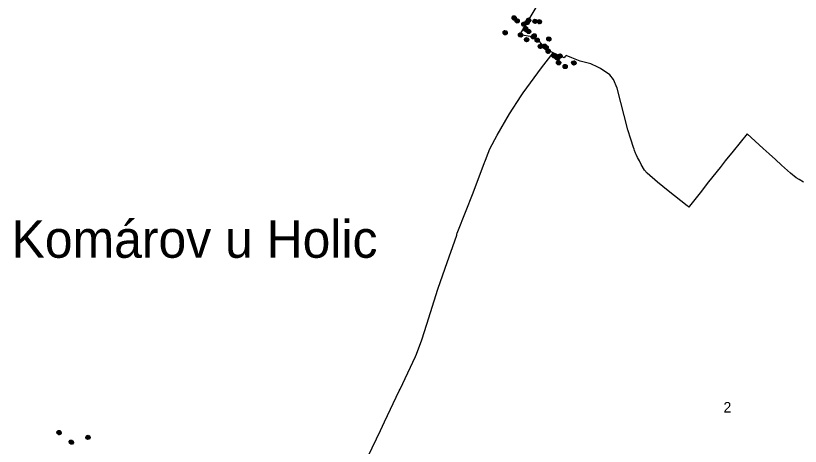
# Model space of a CAD drawing. Extents: x -636174 to -630484, y -1066390 to -1059369.
# Drawn here: x -635533 to -633008, y -1062153 to -1060768 of the extents above; entities that cross this region are included whole.
import ezdxf

# ---------------------------------------------------------------- set-up
doc = ezdxf.new("R2010")
doc.units = 0
for name, color, linetype in [('HRA_KU', 7, 'Continuous'), ('KU_OST', 7, 'Continuous'), ('Level 255', 7, 'Continuous'), ('OVNE_PRE', 7, 'Continuous'), ('OVNE_SET', 7, 'Continuous')]:
    doc.layers.add(name, color=color, linetype=linetype)

msp = doc.modelspace()

# ---------------------------------------------------------------- linework, layer by layer
at = {"layer": 'HRA_KU'}
for points in [[(-633803.1, -1060886.9), (-633821.3, -1060878), (-633833.6, -1060866.4), (-633848.8, -1060849.5), (-633858.7, -1060840.4), (-633863.1, -1060836.3), (-633910.6, -1060829.4), (-633834.8, -1060701.1)], [(-633935.3, -1060777.9), (-633935.4, -1060772.5), (-633931.8, -1060768.6), (-633926.4, -1060768.4), (-633922.4, -1060772.1), (-633922.2, -1060777.4), (-633925.9, -1060781.4), (-633931.3, -1060781.6), (-633935.3, -1060777.9), (-633934.3, -1060777.7), (-633930.7, -1060781), (-633928.5, -1060780.9), (-633934.3, -1060775.5), (-633934.4, -1060773.2), (-633926.2, -1060780.8), (-633925.1, -1060779.7), (-633933.3, -1060772), (-633932.3, -1060770.9), (-633924, -1060778.5), (-633923, -1060777.3), (-633931.2, -1060769.7), (-633928.9, -1060769.6), (-633923, -1060775.1), (-633923.1, -1060772.8), (-633926.6, -1060769.5)], [(-633925.4, -1060787.1), (-633925.6, -1060781.7), (-633921.9, -1060777.8), (-633916.6, -1060777.6), (-633912.6, -1060781.3), (-633912.4, -1060786.6), (-633916.1, -1060790.6), (-633921.5, -1060790.8), (-633925.4, -1060787.1), (-633924.4, -1060786.9), (-633920.9, -1060790.2), (-633918.7, -1060790.1), (-633924.5, -1060784.7), (-633924.6, -1060782.4), (-633916.4, -1060790), (-633915.3, -1060788.9), (-633923.5, -1060781.2), (-633922.4, -1060780.1), (-633914.2, -1060787.7), (-633913.1, -1060786.5), (-633921.3, -1060778.9), (-633919.1, -1060778.8), (-633913.2, -1060784.3), (-633913.3, -1060782), (-633916.8, -1060778.7)], [(-633904.2, -1060797.3), (-633903.9, -1060792), (-633899.9, -1060788.4), (-633894.6, -1060788.6), (-633891, -1060792.7), (-633891.2, -1060798), (-633895.3, -1060801.6), (-633900.6, -1060801.3), (-633904.2, -1060797.3), (-633903.2, -1060797.2), (-633900, -1060800.8), (-633897.8, -1060800.9), (-633903.1, -1060795), (-633903, -1060792.7), (-633895.5, -1060801.1), (-633894.3, -1060800), (-633901.8, -1060791.7), (-633900.6, -1060790.6), (-633893.1, -1060798.9), (-633891.9, -1060797.9), (-633899.4, -1060789.5), (-633897.2, -1060789.6), (-633891.8, -1060795.6), (-633891.7, -1060793.3), (-633894.9, -1060789.8)], [(-633891.4, -1060784.3), (-633886.2, -1060783), (-633881.6, -1060785.8), (-633880.2, -1060791), (-633883, -1060795.6), (-633888.2, -1060796.9), (-633892.8, -1060794.2), (-633894.2, -1060789), (-633891.4, -1060784.3), (-633890.8, -1060784.9), (-633893.3, -1060789.1), (-633892.7, -1060791.2), (-633888.6, -1060784.4), (-633886.4, -1060783.8), (-633892.1, -1060793.4), (-633890.8, -1060794.3), (-633885.1, -1060784.6), (-633883.7, -1060785.4), (-633889.4, -1060795.1), (-633888, -1060795.9), (-633882.3, -1060786.2), (-633881.8, -1060788.4), (-633885.8, -1060795.3), (-633883.6, -1060794.8), (-633881.2, -1060790.6)], [(-633886.8, -1060776.5), (-633881.6, -1060775.1), (-633876.9, -1060777.9), (-633875.6, -1060783.1), (-633878.3, -1060787.7), (-633883.5, -1060789.1), (-633888.2, -1060786.3), (-633889.5, -1060781.1), (-633886.8, -1060776.5), (-633886.2, -1060777.1), (-633888.6, -1060781.2), (-633888.1, -1060783.4), (-633884, -1060776.5), (-633881.8, -1060775.9), (-633887.5, -1060785.6), (-633886.1, -1060786.4), (-633880.4, -1060776.7), (-633879, -1060777.6), (-633884.7, -1060787.2), (-633883.4, -1060788), (-633877.7, -1060778.4), (-633877.1, -1060780.6), (-633881.2, -1060787.4), (-633879, -1060786.9), (-633876.5, -1060782.8)], [(-633867.1, -1060780.9), (-633862.2, -1060778.6), (-633857.1, -1060780.5), (-633854.9, -1060785.4), (-633856.8, -1060790.4), (-633861.6, -1060792.7), (-633866.7, -1060790.8), (-633869, -1060785.9), (-633867.1, -1060780.9), (-633866.4, -1060781.3), (-633868.1, -1060785.8), (-633867.1, -1060787.9), (-633864.4, -1060780.4), (-633862.3, -1060779.4), (-633866.2, -1060789.9), (-633864.7, -1060790.5), (-633860.8, -1060780), (-633859.3, -1060780.5), (-633863.2, -1060791), (-633861.7, -1060791.6), (-633857.8, -1060781.1), (-633856.9, -1060783.1), (-633859.6, -1060790.7), (-633857.6, -1060789.7), (-633855.9, -1060785.2)], [(-633853.2, -1060783.5), (-633848.7, -1060780.5), (-633843.4, -1060781.6), (-633840.5, -1060786), (-633841.5, -1060791.3), (-633846, -1060794.3), (-633851.3, -1060793.2), (-633854.3, -1060788.8), (-633853.2, -1060783.5), (-633852.5, -1060783.8), (-633853.4, -1060788.5), (-633852.1, -1060790.4), (-633850.6, -1060782.6), (-633848.7, -1060781.3), (-633850.9, -1060792.3), (-633849.3, -1060792.6), (-633847.1, -1060781.6), (-633845.6, -1060781.9), (-633847.8, -1060792.9), (-633846.2, -1060793.2), (-633844, -1060782.3), (-633842.7, -1060784.1), (-633844.3, -1060792), (-633842.4, -1060790.7), (-633841.5, -1060786)], [(-633898.6, -1060811.9), (-633898.8, -1060806.6), (-633895.1, -1060802.6), (-633889.8, -1060802.4), (-633885.8, -1060806.1), (-633885.6, -1060811.5), (-633889.3, -1060815.4), (-633894.7, -1060815.6), (-633898.6, -1060811.9), (-633897.9, -1060811.5), (-633894.4, -1060814.8), (-633892.1, -1060814.7), (-633898, -1060809.2), (-633898.1, -1060807), (-633889.9, -1060814.6), (-633888.8, -1060813.4), (-633897, -1060805.8), (-633895.9, -1060804.6), (-633887.7, -1060812.3), (-633886.6, -1060811.1), (-633894.8, -1060803.5), (-633892.6, -1060803.4), (-633886.7, -1060808.8), (-633886.8, -1060806.6), (-633890.3, -1060803.3)], [(-633897.5, -1060815.1), (-633897.7, -1060809.8), (-633894, -1060805.8), (-633888.6, -1060805.7), (-633884.7, -1060809.4), (-633884.5, -1060814.7), (-633888.2, -1060818.7), (-633893.6, -1060818.8), (-633897.5, -1060815.1), (-633896.5, -1060815), (-633893, -1060818.2), (-633890.8, -1060818.2), (-633896.6, -1060812.7), (-633896.7, -1060810.4), (-633888.5, -1060818.1), (-633887.4, -1060816.9), (-633895.6, -1060809.3), (-633894.5, -1060808.1), (-633886.3, -1060815.8), (-633885.2, -1060814.6), (-633893.4, -1060806.9), (-633891.1, -1060806.9), (-633885.3, -1060812.3), (-633885.4, -1060810.1), (-633888.9, -1060806.8)], [(-633888.8, -1060821.1), (-633889, -1060815.8), (-633885.3, -1060811.8), (-633879.9, -1060811.6), (-633876, -1060815.3), (-633875.8, -1060820.7), (-633879.5, -1060824.6), (-633884.8, -1060824.8), (-633888.8, -1060821.1), (-633888.1, -1060820.7), (-633884.6, -1060824), (-633882.3, -1060823.9), (-633888.2, -1060818.4), (-633888.3, -1060816.2), (-633880.1, -1060823.8), (-633879, -1060822.6), (-633887.2, -1060815), (-633886.1, -1060813.8), (-633877.9, -1060821.5), (-633876.8, -1060820.3), (-633885, -1060812.7), (-633882.7, -1060812.6), (-633876.9, -1060818), (-633877, -1060815.8), (-633880.5, -1060812.5)], [(-633961.6, -1060828.6), (-633964.8, -1060824.3), (-633964, -1060818.9), (-633959.7, -1060815.7), (-633954.4, -1060816.5), (-633951.2, -1060820.8), (-633951.9, -1060826.1), (-633956.2, -1060829.4), (-633961.6, -1060828.6), (-633960.9, -1060827.9), (-633956.1, -1060828.6), (-633954.3, -1060827.2), (-633962.2, -1060826.1), (-633963.6, -1060824.3), (-633952.5, -1060825.9), (-633952.3, -1060824.3), (-633963.4, -1060822.7), (-633963.1, -1060821.1), (-633952, -1060822.7), (-633951.8, -1060821.1), (-633962.9, -1060819.5), (-633961.1, -1060818.2), (-633953.2, -1060819.3), (-633954.5, -1060817.5), (-633959.3, -1060816.8)], [(-633912.1, -1060835.7), (-633915.3, -1060831.4), (-633914.5, -1060826.1), (-633910.2, -1060822.8), (-633904.9, -1060823.6), (-633901.7, -1060827.9), (-633902.4, -1060833.2), (-633906.7, -1060836.5), (-633912.1, -1060835.7), (-633911.8, -1060834.9), (-633907, -1060835.6), (-633905.2, -1060834.3), (-633913.1, -1060833.1), (-633914.5, -1060831.3), (-633903.4, -1060832.9), (-633903.2, -1060831.3), (-633914.3, -1060829.7), (-633914, -1060828.1), (-633902.9, -1060829.7), (-633902.7, -1060828.2), (-633913.8, -1060826.6), (-633912, -1060825.2), (-633904.1, -1060826.3), (-633905.4, -1060824.5), (-633910.2, -1060823.9)], [(-633894.4, -1060849.1), (-633896.1, -1060844.1), (-633893.8, -1060839.2), (-633888.7, -1060837.5), (-633883.8, -1060839.9), (-633882.1, -1060844.9), (-633884.5, -1060849.8), (-633889.6, -1060851.5), (-633894.4, -1060849.1), (-633893.5, -1060848.7), (-633889.2, -1060850.8), (-633887.1, -1060850.1), (-633894.2, -1060846.5), (-633895, -1060844.4), (-633884.9, -1060849.3), (-633884.2, -1060847.9), (-633894.3, -1060843), (-633893.6, -1060841.5), (-633883.5, -1060846.5), (-633882.8, -1060845), (-633892.9, -1060840.1), (-633890.7, -1060839.4), (-633883.5, -1060842.9), (-633884.3, -1060840.8), (-633888.6, -1060838.6)], [(-633870.6, -1060841.6), (-633873.8, -1060837.3), (-633873, -1060832), (-633868.7, -1060828.8), (-633863.4, -1060829.5), (-633860.2, -1060833.8), (-633860.9, -1060839.2), (-633865.2, -1060842.4), (-633870.6, -1060841.6), (-633869.9, -1060840.9), (-633865.1, -1060841.6), (-633863.3, -1060840.3), (-633871.2, -1060839.1), (-633872.6, -1060837.3), (-633861.5, -1060838.9), (-633861.3, -1060837.3), (-633872.3, -1060835.7), (-633872.1, -1060834.1), (-633861, -1060835.7), (-633860.8, -1060834.2), (-633871.9, -1060832.6), (-633870.1, -1060831.2), (-633862.2, -1060832.3), (-633863.5, -1060830.5), (-633868.3, -1060829.9)], [(-633870.8, -1060834.5), (-633870.6, -1060829.2), (-633866.5, -1060825.6), (-633861.2, -1060825.9), (-633857.6, -1060829.9), (-633857.9, -1060835.2), (-633861.9, -1060838.9), (-633867.2, -1060838.6), (-633870.8, -1060834.5), (-633870.1, -1060834.2), (-633866.9, -1060837.7), (-633864.7, -1060837.9), (-633870, -1060831.9), (-633869.9, -1060829.6), (-633862.4, -1060838), (-633861.2, -1060836.9), (-633868.7, -1060828.6), (-633867.5, -1060827.5), (-633860, -1060835.8), (-633858.8, -1060834.8), (-633866.3, -1060826.4), (-633864, -1060826.6), (-633858.7, -1060832.5), (-633858.6, -1060830.3), (-633861.8, -1060826.7)], [(-633861.1, -1060849.4), (-633861.3, -1060844), (-633857.6, -1060840.1), (-633852.2, -1060839.9), (-633848.3, -1060843.6), (-633848.1, -1060849), (-633851.8, -1060852.9), (-633857.2, -1060853.1), (-633861.1, -1060849.4), (-633860.4, -1060848.9), (-633856.9, -1060852.2), (-633854.6, -1060852.2), (-633860.5, -1060846.7), (-633860.5, -1060844.4), (-633852.4, -1060852.1), (-633851.3, -1060850.9), (-633859.4, -1060843.2), (-633858.4, -1060842.1), (-633850.2, -1060849.8), (-633849.1, -1060848.6), (-633857.3, -1060840.9), (-633855, -1060840.8), (-633849.2, -1060846.3), (-633849.2, -1060844.1), (-633852.7, -1060840.8)], [(-633821.1, -1060848.8), (-633824.3, -1060844.4), (-633823.5, -1060839.1), (-633819.2, -1060835.9), (-633813.9, -1060836.6), (-633810.7, -1060841), (-633811.4, -1060846.3), (-633815.7, -1060849.5), (-633821.1, -1060848.8), (-633820.8, -1060848), (-633816, -1060848.7), (-633814.2, -1060847.3), (-633822.1, -1060846.2), (-633823.5, -1060844.4), (-633812.4, -1060846), (-633812.2, -1060844.4), (-633823.2, -1060842.8), (-633823, -1060841.2), (-633811.9, -1060842.8), (-633811.7, -1060841.2), (-633822.8, -1060839.6), (-633821, -1060838.3), (-633813.1, -1060839.4), (-633814.4, -1060837.6), (-633819.2, -1060836.9)], [(-633849.6, -1060871.2), (-633851.3, -1060866.1), (-633848.9, -1060861.3), (-633843.8, -1060859.6), (-633839, -1060862), (-633837.2, -1060867), (-633839.6, -1060871.9), (-633844.7, -1060873.6), (-633849.6, -1060871.2), (-633849, -1060870.6), (-633844.7, -1060872.7), (-633842.6, -1060872), (-633849.7, -1060868.5), (-633850.5, -1060866.3), (-633840.4, -1060871.3), (-633839.7, -1060869.8), (-633849.8, -1060864.9), (-633849.1, -1060863.4), (-633839, -1060868.4), (-633838.3, -1060867), (-633848.4, -1060862), (-633846.2, -1060861.3), (-633839, -1060864.8), (-633839.8, -1060862.7), (-633844.1, -1060860.6)], [(-633837.1, -1060869.1), (-633837.3, -1060863.8), (-633833.6, -1060859.8), (-633828.3, -1060859.6), (-633824.3, -1060863.3), (-633824.1, -1060868.7), (-633827.8, -1060872.6), (-633833.2, -1060872.8), (-633837.1, -1060869.1), (-633836.1, -1060869), (-633832.6, -1060872.2), (-633830.3, -1060872.1), (-633836.2, -1060866.7), (-633836.3, -1060864.4), (-633828.1, -1060872.1), (-633827, -1060870.9), (-633835.2, -1060863.3), (-633834.1, -1060862.1), (-633825.9, -1060869.7), (-633824.8, -1060868.5), (-633833, -1060860.9), (-633830.8, -1060860.8), (-633824.9, -1060866.3), (-633825, -1060864), (-633828.5, -1060860.8)], [(-633832.7, -1060873.2), (-633832.9, -1060867.8), (-633829.2, -1060863.9), (-633823.8, -1060863.7), (-633819.9, -1060867.3), (-633819.7, -1060872.7), (-633823.3, -1060876.7), (-633828.7, -1060876.9), (-633832.7, -1060873.2), (-633831.7, -1060873), (-633828.2, -1060876.3), (-633825.9, -1060876.2), (-633831.8, -1060870.8), (-633831.9, -1060868.5), (-633823.6, -1060876.1), (-633822.6, -1060874.9), (-633830.8, -1060867.3), (-633829.7, -1060866.1), (-633821.5, -1060873.8), (-633820.4, -1060872.6), (-633828.6, -1060865), (-633826.3, -1060864.9), (-633820.5, -1060870.3), (-633820.5, -1060868.1), (-633824.1, -1060864.8)], [(-633825.9, -1060884.6), (-633825.6, -1060879.2), (-633821.6, -1060875.6), (-633816.2, -1060875.9), (-633812.6, -1060879.9), (-633812.9, -1060885.3), (-633816.9, -1060888.9), (-633822.3, -1060888.6), (-633825.9, -1060884.6), (-633824.9, -1060884.5), (-633821.7, -1060888.1), (-633819.4, -1060888.2), (-633824.8, -1060882.2), (-633824.7, -1060880), (-633817.2, -1060888.3), (-633816, -1060887.2), (-633823.5, -1060878.9), (-633822.3, -1060877.8), (-633814.8, -1060886.2), (-633813.6, -1060885.1), (-633821.1, -1060876.8), (-633818.8, -1060876.9), (-633813.5, -1060882.8), (-633813.4, -1060880.6), (-633816.6, -1060877)], [(-633807.8, -1060899.4), (-633808, -1060894.1), (-633804.3, -1060890.1), (-633798.9, -1060890), (-633795, -1060893.7), (-633794.8, -1060899), (-633798.5, -1060903), (-633803.9, -1060903.1), (-633807.8, -1060899.4), (-633806.8, -1060899.3), (-633803.3, -1060902.6), (-633801.1, -1060902.5), (-633806.9, -1060897), (-633807, -1060894.7), (-633798.8, -1060902.4), (-633797.7, -1060901.3), (-633805.9, -1060893.6), (-633804.8, -1060892.4), (-633796.6, -1060900.1), (-633795.5, -1060898.9), (-633803.7, -1060891.3), (-633801.4, -1060891.2), (-633795.6, -1060896.7), (-633795.7, -1060894.4), (-633799.2, -1060891.1)], [(-633787, -1060902), (-633788.7, -1060896.9), (-633786.3, -1060892.1), (-633781.2, -1060890.4), (-633776.4, -1060892.7), (-633774.7, -1060897.8), (-633777.1, -1060902.7), (-633782.1, -1060904.4), (-633787, -1060902), (-633786.1, -1060901.6), (-633781.8, -1060903.7), (-633779.6, -1060903), (-633786.8, -1060899.4), (-633787.5, -1060897.3), (-633777.5, -1060902.2), (-633776.8, -1060900.8), (-633786.8, -1060895.9), (-633786.1, -1060894.4), (-633776.1, -1060899.4), (-633775.4, -1060897.9), (-633785.4, -1060893), (-633783.3, -1060892.3), (-633776.1, -1060895.8), (-633776.8, -1060893.6), (-633781.1, -1060891.5)], [(-633800.5, -1060903.2), (-633800.7, -1060897.8), (-633797, -1060893.8), (-633791.6, -1060893.6), (-633787.7, -1060897.3), (-633787.5, -1060902.7), (-633791.1, -1060906.6), (-633796.5, -1060906.8), (-633800.5, -1060903.2), (-633799.8, -1060902.7), (-633796.3, -1060906), (-633794, -1060905.9), (-633799.9, -1060900.5), (-633800, -1060898.2), (-633791.7, -1060905.8), (-633790.7, -1060904.7), (-633798.9, -1060897), (-633797.8, -1060895.9), (-633789.6, -1060903.5), (-633788.5, -1060902.3), (-633796.7, -1060894.7), (-633794.4, -1060894.6), (-633788.6, -1060900), (-633788.6, -1060897.8), (-633792.2, -1060894.5)], [(-633796, -1060907.2), (-633796.2, -1060901.9), (-633792.6, -1060897.9), (-633787.2, -1060897.7), (-633783.2, -1060901.4), (-633783, -1060906.7), (-633786.7, -1060910.7), (-633792.1, -1060910.9), (-633796, -1060907.2), (-633795.3, -1060906.8), (-633791.8, -1060910), (-633789.6, -1060910), (-633795.4, -1060904.5), (-633795.5, -1060902.2), (-633787.3, -1060909.9), (-633786.2, -1060908.7), (-633794.4, -1060901.1), (-633793.3, -1060899.9), (-633785.1, -1060907.5), (-633784, -1060906.4), (-633792.2, -1060898.7), (-633790, -1060898.6), (-633784.1, -1060904.1), (-633784.2, -1060901.8), (-633787.7, -1060898.6)], [(-633792.5, -1060921.8), (-633792.2, -1060916.4), (-633788.2, -1060912.8), (-633782.8, -1060913.1), (-633779.2, -1060917.1), (-633779.5, -1060922.5), (-633783.5, -1060926.1), (-633788.9, -1060925.8), (-633792.5, -1060921.8), (-633791.8, -1060921.4), (-633788.6, -1060925), (-633786.3, -1060925.1), (-633791.7, -1060919.2), (-633791.5, -1060916.9), (-633784.1, -1060925.2), (-633782.9, -1060924.2), (-633790.3, -1060915.8), (-633789.2, -1060914.8), (-633781.7, -1060923.1), (-633780.5, -1060922), (-633788, -1060913.7), (-633785.7, -1060913.8), (-633780.4, -1060919.8), (-633780.2, -1060917.5), (-633783.4, -1060913.9)], [(-633742.1, -1060924.1), (-633743.9, -1060919), (-633741.5, -1060914.2), (-633736.4, -1060912.5), (-633731.5, -1060914.8), (-633729.8, -1060919.9), (-633732.2, -1060924.8), (-633737.3, -1060926.5), (-633742.1, -1060924.1), (-633741.6, -1060923.5), (-633737.3, -1060925.6), (-633735.1, -1060924.9), (-633742.3, -1060921.3), (-633743.1, -1060919.2), (-633733, -1060924.1), (-633732.3, -1060922.7), (-633742.3, -1060917.8), (-633741.6, -1060916.3), (-633731.6, -1060921.3), (-633730.9, -1060919.8), (-633740.9, -1060914.9), (-633738.8, -1060914.2), (-633731.6, -1060917.7), (-633732.3, -1060915.6), (-633736.6, -1060913.4)], [(-633771.4, -1060933.7), (-633771.6, -1060928.3), (-633767.9, -1060924.4), (-633762.5, -1060924.2), (-633758.6, -1060927.9), (-633758.4, -1060933.3), (-633762.1, -1060937.2), (-633767.5, -1060937.4), (-633771.4, -1060933.7), (-633770.7, -1060933.2), (-633767.2, -1060936.5), (-633764.9, -1060936.5), (-633770.8, -1060931), (-633770.8, -1060928.7), (-633762.7, -1060936.4), (-633761.6, -1060935.2), (-633769.7, -1060927.6), (-633768.6, -1060926.4), (-633760.5, -1060934.1), (-633759.4, -1060932.9), (-633767.6, -1060925.2), (-633765.3, -1060925.2), (-633759.5, -1060930.6), (-633759.5, -1060928.4), (-633763, -1060925.1)], [(-635399.3, -1062111.9), (-635399.9, -1062106.5), (-635396.6, -1062102.3), (-635391.2, -1062101.7), (-635387, -1062105), (-635386.3, -1062110.3), (-635389.7, -1062114.6), (-635395, -1062115.2), (-635399.3, -1062111.9), (-635398.3, -1062111.6), (-635394.5, -1062114.6), (-635392.3, -1062114.3), (-635398.6, -1062109.4), (-635398.8, -1062107.1), (-635390, -1062114), (-635389, -1062112.8), (-635397.8, -1062105.9), (-635396.9, -1062104.6), (-635388.1, -1062111.5), (-635387.1, -1062110.3), (-635395.9, -1062103.3), (-635393.6, -1062103.1), (-635387.3, -1062108), (-635387.6, -1062105.8), (-635391.4, -1062102.8)], [(-635295.7, -1062129.4), (-635300.8, -1062131), (-635305.6, -1062128.5), (-635307.3, -1062123.4), (-635304.8, -1062118.6), (-635299.7, -1062117), (-635294.9, -1062119.4), (-635293.2, -1062124.5), (-635295.7, -1062129.4), (-635296.3, -1062128.8), (-635294.1, -1062124.5), (-635294.8, -1062122.4), (-635298.5, -1062129.5), (-635300.6, -1062130.2), (-635295.5, -1062120.2), (-635296.9, -1062119.5), (-635302, -1062129.5), (-635303.5, -1062128.7), (-635298.4, -1062118.8), (-635299.8, -1062118), (-635304.9, -1062128), (-635305.6, -1062125.8), (-635301.9, -1062118.7), (-635304.1, -1062119.4), (-635306.3, -1062123.7)], [(-635360, -1062142.8), (-635360.6, -1062137.4), (-635357.3, -1062133.2), (-635351.9, -1062132.6), (-635347.7, -1062135.9), (-635347.1, -1062141.2), (-635350.4, -1062145.5), (-635355.7, -1062146.1), (-635360, -1062142.8), (-635359.3, -1062142.3), (-635355.5, -1062145.2), (-635353.3, -1062145), (-635359.6, -1062140), (-635359.9, -1062137.8), (-635351.1, -1062144.7), (-635350.1, -1062143.5), (-635358.9, -1062136.5), (-635357.9, -1062135.3), (-635349.1, -1062142.2), (-635348.1, -1062140.9), (-635356.9, -1062134), (-635354.6, -1062133.7), (-635348.4, -1062138.7), (-635348.6, -1062136.4), (-635352.4, -1062133.5)]]:
    msp.add_lwpolyline(points, dxfattribs=at)
at = {"layer": 'OVNE_PRE'}
msp.add_lwpolyline([(-632997.8, -1061303.1), (-633011.7, -1061294.7), (-633021.2, -1061288.9), (-633039.4, -1061274.1), (-633049.3, -1061266.1), (-633068.4, -1061248.7), (-633088.1, -1061230.7), (-633108.2, -1061212.4), (-633127.5, -1061194.9), (-633179.5, -1061147.8), (-633224.7, -1061203.8), (-633249.5, -1061234.5), (-633266, -1061255.5), (-633303.1, -1061302.4), (-633330.5, -1061337.1), (-633364.6, -1061380.4), (-633367.2, -1061383.7), (-633369.5, -1061381.9), (-633372.3, -1061379.6), (-633433.1, -1061331.1), (-633467.2, -1061302.7), (-633501.1, -1061274.3), (-633509.5, -1061264.4), (-633519.8, -1061246), (-633525.9, -1061235.1), (-633532.3, -1061223.6), (-633536.2, -1061214.2), (-633538.1, -1061209.6), (-633541.8, -1061200.8), (-633543.2, -1061197.4), (-633545.2, -1061191.6), (-633553.8, -1061165.2), (-633563.6, -1061135.2), (-633597.2, -1061000.6), (-633608.9, -1060973), (-633620.9, -1060957.5), (-633650.7, -1060937.9), (-633660.2, -1060933.3), (-633682.4, -1060922.7), (-633716.6, -1060914.5), (-633743.6, -1060903), (-633761.6, -1060895.3), (-633766.2, -1060900.3), (-633768.5, -1060902.8), (-633803.1, -1060886.9)], dxfattribs=at)
at = {"layer": 'OVNE_SET'}
msp.add_lwpolyline([(-634399, -1062184.7), (-634359.2, -1062102), (-634346.1, -1062074.5), (-634298.5, -1061973.9), (-634296.2, -1061969.1), (-634246.4, -1061863.8), (-634242.8, -1061856.2), (-634226.5, -1061810.7), (-634209.6, -1061759.6), (-634174.2, -1061646.9), (-634151.3, -1061579.3), (-634113.4, -1061474.1), (-634112.9, -1061468.9), (-634112.7, -1061467.3), (-634110.6, -1061462.1), (-634061, -1061337.5), (-634024, -1061239.6), (-634023.2, -1061237.5), (-634019.2, -1061227), (-634018.1, -1061224.1), (-634007.6, -1061196.1), (-633983.2, -1061151.5), (-633943.6, -1061083.7), (-633906.5, -1061025.4), (-633899.6, -1061015.9), (-633840.9, -1060935.3), (-633803.1, -1060886.9)], dxfattribs=at)

# ---------------------------------------------------------------- texts
at = {"layer": 'KU_OST'}
msp.add_text('Komárov u Holic', height=120, dxfattribs=at).set_placement((-635545.9, -1061546.4))
at = {"layer": 'Level 255'}
msp.add_text('2', height=34, dxfattribs=at).set_placement((-633255.5, -1062044.4))

doc.saveas('drawing.dxf')
